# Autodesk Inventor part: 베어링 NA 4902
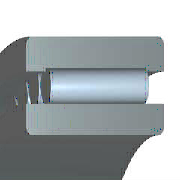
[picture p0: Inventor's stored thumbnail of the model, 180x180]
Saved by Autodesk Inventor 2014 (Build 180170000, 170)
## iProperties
IsCustomPart: 0
Manager: KYOUNG IL JANG
Company: 한국ATC센터
Created: 2009-02
Part Number: 베어링 NA 4902
Material: Steel, Mild
Description: 니들 롤러 베어링 - 경계 치수 및 공차
Document SubType Name: Modeling
Standard: KS B 2029
Standards Organization: KS
Language: ko-KR
Size Designation: NA 4902 - 15 x 28 x 13
Categories: <MemberInstance><Categories><Category DisplayName="샤프트 부품" InternalName="7f7aeb1f-a693-4053-b835-cee3144e0d98" Mnemonic="SHFT"><Category DisplayName="베어링" Inter
Density: 1 g/cm^3
Checked By: KYOUNG IL JANG
Vendor: CBT Solutions
Designer: KYOUNG IL JANG
Appearance: _시험-파란색 크롬
Author: KYOUNG IL JANG
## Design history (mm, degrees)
sketch "스케치"
  geometry: L1 (1.857, 11.5)-(11.143, 11.5); L2 (11.143, 11.5)-(11.143, 10); L3 (13, 10)-(0, 10); L4 (1.857, 10)-(1.857, 11.5); L5 (1.857, 10.75)-(11.143, 10.75); L6 (6.5, 10.75)-(6.5, 10); L7 (0, 7.5)-(13, 7.5); L8 (0, 14)-(13, 14); L9 (13, 7.5)-(13, 10); L10 (13, 11.35)-(13, 14); L11 (1.857, 11.35)-(0, 11.35); L12 (11.143, 11.35)-(13, 11.35); L13 (-6, 0)-(36, 0) reference; L14 (0, -1.9)-(0, 14.9) reference
  constraints: 24 end point, 8 point on line, 3 midpoint, 3 parallel, 3 perpendicular, 2 symmetric about line, 1 horizontal, 1 other
  dimensions: "d6" = 15 diameter of L7 L13 (= WD); "d7" = 20 diameter of L3 L13 (= KID1); "d8" = 28 diameter of L8 L13 (= BD); "d9" = 21.5 diameter of L6.start L13 (= 0.5 x WD + 0.5 x BD); "d10" = 22.7 diameter of L12 L13 (= 0.9 x BD + 0.9 x WD - 0.8 x KID1); "d11" = 23 diameter of L1 L13 (= BD + WD - KID1); "d12" = 1.85714 distance between parallel lines of L14 L4 (= 0.142857 x KB); "d13" = 13 distance between parallel lines of L14 L9 (= KB); "d14" = 11.14286 distance between parallel lines of L14 L2 (= 0.857143 x KB)
revolve "본체" stored, may be unused: angle "d17" = 90 deg
revolve "롤러" stored, may be unused: angle "d18" = 90 deg
body "Solid1"
fillet "모깎기1" dims "d0" = 0.3 (= KRS)
pattern_circular "IDS_ARRAYROLLER[SIMPL:T]" dims angle "d2" = 360 deg
other parameters: "WD" = 15 [user parameter; used in 6 equation terms], "BD" = 28 [user parameter; used in 6 equation terms], "KB" = 13 [user parameter; used in 3 equation terms], "KID1" = 20 [user parameter; used in 4 equation terms], "KRS" = 0.3 [user parameter; used in 1 equation term], "d3" = 0, "d4" = 0, "d5" = 0, "d15" = 0, "d16" = 0, "BC0" = 1.37e+07 [user parameter], "WR" = 7.5 (= 0.5 x WD) [user parameter], "BBA" = 0 [user parameter], "BC" = 1.02e+07 [user parameter], "BR" = 14 (= 0.5 x BD) [user parameter]
